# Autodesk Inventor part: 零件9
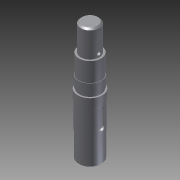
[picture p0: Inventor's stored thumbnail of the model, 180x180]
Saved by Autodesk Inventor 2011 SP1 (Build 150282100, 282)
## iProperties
Created: 2014-02
Part Number: 零件9
Document SubType Name: Modeling
Designer: yn
Density: 1 g/cm^3
Author: yn
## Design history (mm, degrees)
sketch "草图1"
  geometry: C1 r 15 at (0, 0); 1 further point
  constraints: 1 centre point, 1 coincident
  dimensions: "d0" = 30 diameter of C1
extrude "拉伸1" new body sketch "草图1" distance "d1" = 35; taper "d2" = 0 deg
sketch "草图2"
  geometry: C1 r 15.5 at (0, 0); 1 further point
  constraints: 1 centre point, 1 coincident
  dimensions: "d3" = 31 diameter of C1
extrude "拉伸2" join sketch "草图2" distance "d4" = 35; taper "d5" = 0 deg
sketch "草图3"
  geometry: C1 r 16 at (0, 0); 1 further point
  constraints: 1 centre point, 1 coincident
  dimensions: "d6" = 32 diameter of C1
extrude "拉伸3" join sketch "草图3" distance "d7" = 10; taper "d8" = 0 deg
sketch "草图4"
  geometry: C1 r 14 at (0, 0); 1 further point
  constraints: 1 centre point, 1 coincident
  dimensions: "d9" = 28 diameter of C1
extrude "拉伸4" join sketch "草图4" distance "d10" = 3; taper "d11" = 0 deg
sketch "草图5"
  geometry: C1 r 15 at (0, 0); 1 further point
  constraints: 1 centre point, 1 coincident
  dimensions: "d12" = 30 diameter of C1
extrude "拉伸5" join sketch "草图5" distance "d13" = 13; taper "d14" = 0 deg
sketch "草图6"
  geometry: C1 r 14.5 at (0, 0); 1 further point
  constraints: 1 centre point, 1 coincident
  dimensions: "d15" = 29 diameter of C1
extrude "拉伸6" join sketch "草图6" distance "d16" = 25; taper "d17" = 0 deg
sketch "草图7"
  geometry: C1 r 12 at (0, 0); 1 further point
  constraints: 1 centre point, 1 coincident
  dimensions: "d18" = 24 diameter of C1
extrude "拉伸7" join sketch "草图7" distance "d19" = 35; taper "d20" = 0 deg
chamfer "倒角1" distance "d21" = 2; stored, may be unused: second distance "d22" = 2, angle "d23" = 45 deg
node "工作平面1"
node "工作平面2"
sketch "草图8"
  geometry: L1 (12, 121)-(12, 154) reference; L2 (-12, 121)-(-12, 154) reference; L3 (12, 154)-(-12, 154) reference; L4 (-12, 121)-(12, 121) reference; L5 (2.5, 149.158)-(2.5, 125.623); L6 (-2.5, 149.158)-(-2.488, 125.621); A1 r 2.5 centre (0, 149.186) between (2.5, 149.158) and (-2.5, 149.158); A2 r 2.494 centre (0.006, 125.623) between (-2.488, 125.621) and (2.5, 125.623); 1 further point
  constraints: 4 end point, 4 point on circle, 2 centre point, 2 tangent
extrude "拉伸8" cut sketch "草图8" distance "d26" = 3; taper "d27" = 0 deg
sketch "草图9"
  geometry: L1 (-15.5, 70)-(15.5, 70) reference; L2 (-15.5, 35)-(15.5, 35) reference; L3 (15.5, 35)-(15.5, 70) reference; L4 (-15.5, 35)-(-15.5, 70) reference; L5 (4, 61.953)-(4, 43.039); L6 (-4, 61.953)-(-4, 43.039); A1 r 4 centre (0, 61.953) between (4, 61.953) and (-4, 61.953); A2 r 4 centre (0, 43.039) between (-4, 43.039) and (4, 43.039); 1 further point
  constraints: 4 end point, 4 point on circle, 2 centre point, 2 parallel, 2 tangent
  dimensions: "d28" = 8 diameter of A1; "d30" = 8 diameter of A2
extrude "拉伸9" cut sketch "草图9" distance "d31" = 3; taper "d32" = 0 deg
node "实体1"
node "投影回路1"
other parameters: "d24" = 9, "d25" = 12.5
